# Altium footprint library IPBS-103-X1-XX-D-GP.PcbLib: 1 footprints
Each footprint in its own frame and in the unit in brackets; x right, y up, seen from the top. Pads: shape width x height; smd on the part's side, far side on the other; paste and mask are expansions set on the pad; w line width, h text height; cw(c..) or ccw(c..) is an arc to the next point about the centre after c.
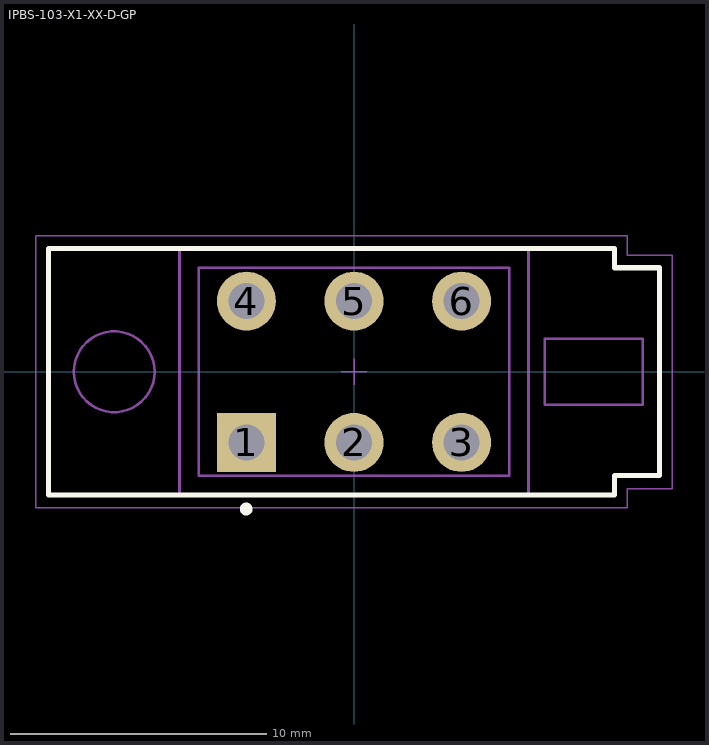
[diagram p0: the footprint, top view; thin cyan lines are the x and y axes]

## IPBS-103-X1-XX-D-GP [mm] "4.19mm pitch, power-mate socket; double row"
height 13.84
pads (6):
  rect 2.3x2.3 / inner round 2.3 / far side rect 2.3x2.3 hole 1.4 mask+0: 1(-4.191,-2.756)
  round 2.3 hole 1.4 mask+0: 2(0,-2.756) 3(4.191,-2.756) 4(-4.191,2.756) 5(0,2.756) 6(4.191,2.756)
Top Overlay:
  circle w0.25: c-4.2,-5.35 r0.125
  lines w0.2: -11.9,-4.8 -11.9,4.8 10.15,4.8 10.15,4.051 11.9,4.051 11.9,-4.05 10.15,-4.05 10.15,-4.8 -11.9,-4.8
Mechanical 12:
  lines w0.001: -11.9,-4.8 -11.9,4.8 10.15,4.8 10.15,4.051 11.9,4.051 11.9,-4.05 10.15,-4.05 10.15,-4.8 -11.9,-4.8
Mechanical 13:
  circle w0.1: c-9.347,0 r1.575
  lines w0.1: -6.8,-4.8 -6.8,4.8 ; 6.8,-4.8 6.8,4.8 ; -11.9,-4.8 -11.9,4.8 10.15,4.8 10.15,4.051 11.9,4.051 11.9,-4.05 10.15,-4.05 10.15,-4.8 -11.9,-4.8 ; -6.045,-4.051 -6.045,4.051 6.045,4.051 6.045,-4.051 -6.045,-4.051 ; 7.442,-1.283 7.442,1.283 11.252,1.283 11.252,-1.283 7.442,-1.283
  text ".Designator" at 0.254,0.254 h1.52
Mechanical 15:
  lines w0.05: -0.5,0 0.5,0 ; 0,-0.5 0,0.5 ; -12.4,-5.3 -12.4,5.3 10.65,5.3 10.65,4.55 12.4,4.55 12.4,-4.55 10.65,-4.55 10.65,-5.3 -12.4,-5.3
